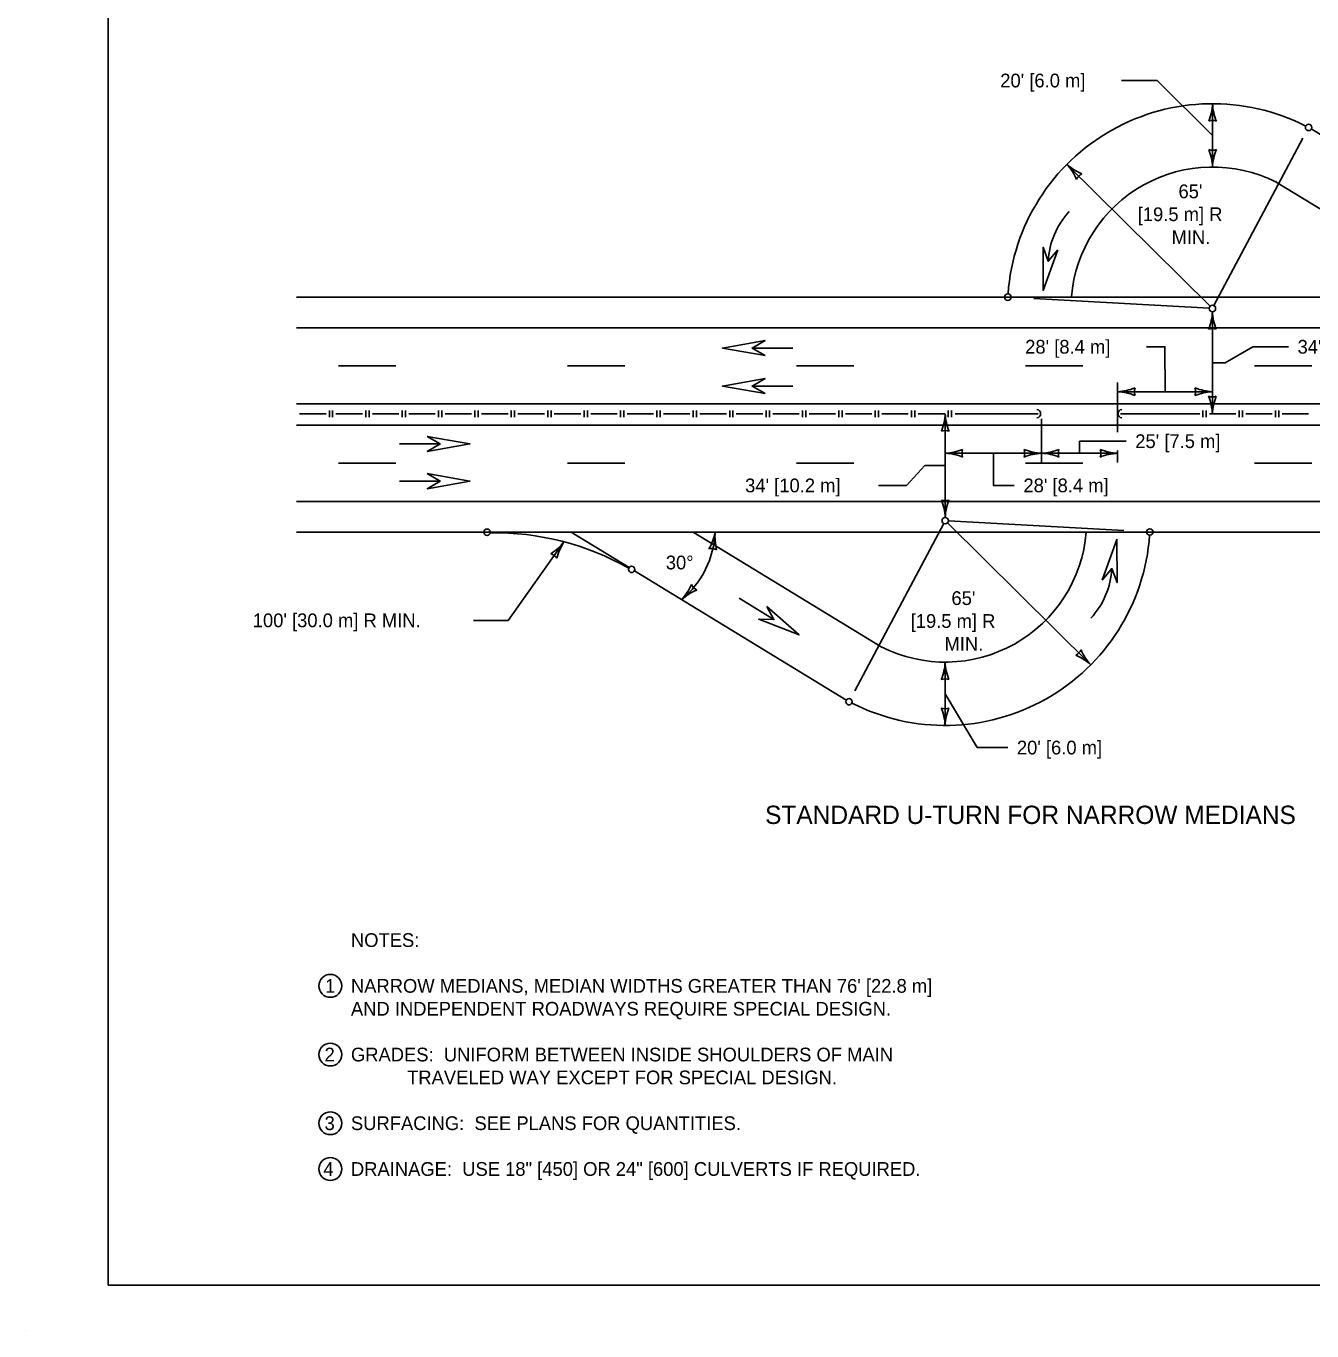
# Model space of a CAD drawing. Extents: x 49991.4 to 50021, y 49987.6 to 50011.4.
# Drawn here: x 49999.98 to 50005.59, y 49999.86 to 50005.56 of the extents above; entities that cross this region are included whole.
import ezdxf

# ---------------------------------------------------------------- set-up
doc = ezdxf.new("R2010")
doc.units = 0
for name, color, linetype in [('Level 1', 7, 'Continuous'), ('Level 2', 7, 'Continuous'), ('Level 3', 7, 'Continuous')]:
    doc.layers.add(name, color=color, linetype=linetype)

msp = doc.modelspace()

# ---------------------------------------------------------------- linework, layer by layer
at = {"layer": 'Level 1'}
for p, q in [((50006.5134, 50004.5478), (50005.5905, 50005.1118)), ((50006.2573, 50004.3784), (50005.4358, 50004.8804)), ((50001.1572, 50004.3784), (50007.9905, 50004.3784)), ((50001.1572, 50004.2451), (50007.9905, 50004.2451)), ((50003.3244, 50004.1562), (50003.1465, 50004.1562)), ((50001.3404, 50004.0784), (50001.5904, 50004.0784)), ((50002.3404, 50004.0784), (50002.5904, 50004.0784)), ((50003.3404, 50004.0784), (50003.5904, 50004.0784)), ((50004.3404, 50004.0784), (50004.5904, 50004.0784)), ((50005.3404, 50004.0784), (50005.5904, 50004.0784)), ((50003.3244, 50003.9897), (50003.1465, 50003.9897)), ((50001.1572, 50003.9118), (50007.9905, 50003.9118)), ((50001.3007, 50003.8548), (50001.3007, 50003.8836)), ((50001.3152, 50003.8548), (50001.3152, 50003.8836)), ((50001.4596, 50003.8548), (50001.4596, 50003.8836)), ((50001.4741, 50003.8548), (50001.4741, 50003.8836)), ((50001.6186, 50003.8548), (50001.6186, 50003.8836)), ((50001.633, 50003.8548), (50001.633, 50003.8836)), ((50001.7775, 50003.8548), (50001.7775, 50003.8836)), ((50001.7919, 50003.8548), (50001.7919, 50003.8836)), ((50001.9364, 50003.8548), (50001.9364, 50003.8836)), ((50001.9508, 50003.8548), (50001.9508, 50003.8836)), ((50002.0953, 50003.8548), (50002.0953, 50003.8836)), ((50002.1098, 50003.8548), (50002.1098, 50003.8836)), ((50002.2542, 50003.8548), (50002.2542, 50003.8836)), ((50002.2687, 50003.8548), (50002.2687, 50003.8836)), ((50002.4131, 50003.8548), (50002.4131, 50003.8836)), ((50002.4276, 50003.8548), (50002.4276, 50003.8836)), ((50002.5721, 50003.8548), (50002.5721, 50003.8836)), ((50002.5865, 50003.8548), (50002.5865, 50003.8836)), ((50002.731, 50003.8548), (50002.731, 50003.8836)), ((50002.7454, 50003.8548), (50002.7454, 50003.8836)), ((50002.8899, 50003.8548), (50002.8899, 50003.8836)), ((50002.9043, 50003.8548), (50002.9043, 50003.8836)), ((50003.0488, 50003.8548), (50003.0488, 50003.8836)), ((50003.0632, 50003.8548), (50003.0632, 50003.8836)), ((50003.2077, 50003.8548), (50003.2077, 50003.8836)), ((50003.2222, 50003.8548), (50003.2222, 50003.8836)), ((50003.3666, 50003.8548), (50003.3666, 50003.8836)), ((50003.3811, 50003.8548), (50003.3811, 50003.8836)), ((50003.5255, 50003.8548), (50003.5255, 50003.8836)), ((50003.54, 50003.8548), (50003.54, 50003.8836)), ((50003.6845, 50003.8548), (50003.6845, 50003.8836)), ((50003.6989, 50003.8548), (50003.6989, 50003.8836)), ((50003.8434, 50003.8548), (50003.8434, 50003.8836)), ((50003.8578, 50003.8548), (50003.8578, 50003.8836)), ((50004.0023, 50003.8548), (50004.0023, 50003.8836)), ((50004.0167, 50003.8548), (50004.0167, 50003.8836)), ((50005.1147, 50003.8548), (50005.1147, 50003.8836)), ((50005.1291, 50003.8548), (50005.1291, 50003.8836)), ((50005.2736, 50003.8548), (50005.2736, 50003.8836)), ((50005.288, 50003.8548), (50005.288, 50003.8836)), ((50005.4325, 50003.8548), (50005.4325, 50003.8836)), ((50005.447, 50003.8548), (50005.447, 50003.8836)), ((50007.9905, 50003.8192), (50001.1572, 50003.8192)), ((50001.6072, 50003.7372), (50001.7851, 50003.7372)), ((50001.3404, 50003.6525), (50001.5904, 50003.6525)), ((50002.3404, 50003.6525), (50002.5904, 50003.6525)), ((50003.3404, 50003.6525), (50003.5904, 50003.6525)), ((50004.3404, 50003.6525), (50004.5904, 50003.6525)), ((50005.3404, 50003.6525), (50005.5904, 50003.6525)), ((50001.6072, 50003.5746), (50001.7851, 50003.5746)), ((50007.9905, 50003.4859), (50001.1572, 50003.4859)), ((50007.9905, 50003.3525), (50001.1572, 50003.3525)), ((50002.3563, 50003.3525), (50002.6096, 50003.1977)), ((50002.8897, 50003.3525), (50003.711, 50002.8506)), ((50002.6339, 50003.1829), (50003.5563, 50002.6192)), ((50003.0901, 50003.0628), (50003.2419, 50002.97)), ((49999.9766, 49999.8624), (49999.9766, 49999.8624))]:
    msp.add_line(p, q, dxfattribs=at)
for points in [[(50008.6146, 50011.2628), (50000.3356, 50011.2628), (50000.3356, 50000.0624), (50008.6146, 50000.0624)], [(50004.4819, 50004.5852), (50004.4172, 50004.4076), (50004.4171, 50004.5967), (50004.4397, 50004.535)], [(50003.2034, 50004.1234), (50003.0172, 50004.1562), (50003.2034, 50004.1892), (50003.1466, 50004.1562)], [(50003.2034, 50003.9569), (50003.0172, 50003.9897), (50003.2034, 50004.0227), (50003.1466, 50003.9897)], [(50001.7282, 50003.7702), (50001.9144, 50003.7374), (50001.7282, 50003.7044), (50001.785, 50003.7374)], [(50001.7282, 50003.6076), (50001.9144, 50003.5748), (50001.7282, 50003.5418), (50001.785, 50003.5748)], [(50004.6753, 50003.1427), (50004.74, 50003.3203), (50004.7401, 50003.1312), (50004.7175, 50003.1929)], [(50003.2105, 50003.0277), (50003.3522, 50002.9026), (50003.1761, 50002.9715), (50003.2418, 50002.9701)]]:
    msp.add_lwpolyline(points, close=True, dxfattribs=at)
for points in [[(50001.1707, 50003.8692), (50001.2863, 50003.8692)], [(50001.3296, 50003.8692), (50001.4452, 50003.8692)], [(50001.4885, 50003.8692), (50001.6041, 50003.8692)], [(50001.6475, 50003.8692), (50001.763, 50003.8692)], [(50001.8064, 50003.8692), (50001.9219, 50003.8692)], [(50001.9653, 50003.8692), (50002.0809, 50003.8692)], [(50002.1242, 50003.8692), (50002.2398, 50003.8692)], [(50002.2831, 50003.8692), (50002.3987, 50003.8692)], [(50002.442, 50003.8692), (50002.5576, 50003.8692)], [(50002.601, 50003.8692), (50002.7165, 50003.8692)], [(50002.7599, 50003.8692), (50002.8754, 50003.8692)], [(50002.9188, 50003.8692), (50003.0343, 50003.8692)], [(50003.0777, 50003.8692), (50003.1933, 50003.8692)], [(50003.2366, 50003.8692), (50003.3522, 50003.8692)], [(50003.3955, 50003.8692), (50003.5111, 50003.8692)], [(50003.5544, 50003.8692), (50003.67, 50003.8692)], [(50003.7133, 50003.8692), (50003.8289, 50003.8692)], [(50003.8722, 50003.8692), (50003.9886, 50003.8692)], [(50004.0336, 50003.8692), (50004.3957, 50003.8692)], [(50004.7555, 50003.8692), (50005.1025, 50003.8692)], [(50005.1436, 50003.8692), (50005.2592, 50003.8692)], [(50005.3025, 50003.8692), (50005.4181, 50003.8692)], [(50005.4614, 50003.8692), (50005.577, 50003.8692)]]:
    msp.add_lwpolyline(points, dxfattribs=at)
for centre in [(50005.5768, 50005.1199), (50004.2634, 50004.3784), (50001.9894, 50003.3516), (50004.8834, 50003.3526), (50002.6207, 50003.1892), (50003.57, 50002.611)]:
    msp.add_circle(centre, 0.014, dxfattribs=at)
for centre, radius, start, end in [((50005.1572, 50004.3284), 0.8952, 62.9695, 175.9019), ((50005.1572, 50004.3284), 0.8952, 61.049, 61.1752), ((50005.1572, 50004.3284), 0.6184, 63.2177, 175.2872), ((50004.7883, 50004.5156), 0.3492, 137.3302, 176.8211), ((50004.3884, 50003.8696), 0.0183, 276.655, 82.9237), ((50004.7628, 50003.8696), 0.0183, 97.0763, 263.345), ((50003.9896, 50003.4025), 0.6184, 243.2177, 355.2872), ((50002.0184, 50002.1501), 1.1993, 60.566, 90.7233), ((50003.9896, 50003.4025), 0.8952, 242.9695, 355.9019), ((50004.3689, 50003.2123), 0.3492, 317.3302, 356.8211), ((50003.9896, 50003.4025), 0.8952, 241.049, 241.1752)]:
    msp.add_arc(centre, radius, start, end, dxfattribs=at)
at = {"layer": 'Level 2'}
for centre in [(50001.305, 50001.3697), (50001.305, 50001.0697), (50001.305, 50000.7697), (50001.305, 50000.5697)]:
    msp.add_circle(centre, 0.05, dxfattribs=at)
at = {"layer": 'Level 3'}
for p, q in [((50004.9158, 50005.3248), (50004.7596, 50005.3248)), ((50005.1572, 50005.0852), (50004.9158, 50005.3248)), ((50005.1572, 50004.9468), (50005.1572, 50005.2236)), ((50005.1633, 50004.3413), (50005.5514, 50005.0723)), ((50005.1467, 50004.3388), (50004.5214, 50004.9586)), ((50005.1427, 50004.3297), (50004.3773, 50004.3721)), ((50005.1567, 50004.3149), (50005.1567, 50003.8692)), ((50005.2131, 50004.092), (50005.3325, 50004.1617)), ((50005.4885, 50004.1617), (50005.3325, 50004.1617)), ((50005.1567, 50004.092), (50005.2131, 50004.092)), ((50004.7429, 50004.0055), (50004.7429, 50003.7892)), ((50005.1567, 50003.9655), (50004.7429, 50003.9655)), ((50003.9901, 50003.4161), (50003.9901, 50003.8692)), ((50004.4106, 50003.6564), (50004.4106, 50003.8472)), ((50003.9901, 50003.6964), (50004.4106, 50003.6964)), ((50004.4106, 50003.6964), (50004.7429, 50003.6964)), ((50004.7429, 50003.6964), (50004.7429, 50003.7092)), ((50004.7429, 50003.6964), (50004.7429, 50003.6564)), ((50003.9835, 50003.3897), (50003.5954, 50002.6587)), ((50004.0001, 50003.3922), (50004.6254, 50002.7724)), ((50004.0041, 50003.4013), (50004.7696, 50003.3589)), ((50002.0819, 50002.9666), (50002.3251, 50003.3095)), ((50001.9301, 50002.9666), (50002.0819, 50002.9666)), ((50003.9896, 50002.7841), (50003.9896, 50002.5073)), ((50003.9896, 50002.6457), (50004.129, 50002.4108)), ((50004.129, 50002.4108), (50004.2629, 50002.4108))]:
    msp.add_line(p, q, dxfattribs=at)
for points in [[(50004.9498, 50003.9655), (50004.9496, 50004.1617), (50004.8683, 50004.1617)], [(50004.2003, 50003.6964), (50004.2004, 50003.5559), (50004.2915, 50003.5559)], [(50004.5768, 50003.6964), (50004.5769, 50003.7492), (50004.7798, 50003.7492)], [(50003.9901, 50003.6427), (50003.9003, 50003.6427), (50003.8207, 50003.5559), (50003.6993, 50003.5559)]]:
    msp.add_lwpolyline(points, dxfattribs=at)
for centre in [(50005.1567, 50004.3289), (50003.9901, 50003.4021)]:
    msp.add_circle(centre, 0.014, dxfattribs=at)
for centre, radius, start, end in [((50004.9351, 50005.2328), 0.2223, 337.456, 357.6395), ((50005.3899, 50005.2351), 0.233, 182.8273, 202.0772), ((50005.1572, 50005.0954), 0.0548, 72.1388, 107.8612), ((50005.1572, 50005.0751), 0.0548, 252.1388, 287.8612), ((50004.9245, 50004.9354), 0.233, 2.8273, 22.0772), ((50005.3793, 50004.9377), 0.2223, 157.456, 177.6395), ((50004.3585, 50004.8073), 0.2223, 22.7092, 42.8927), ((50004.677, 50005.132), 0.233, 228.0805, 247.3303), ((50004.6124, 50004.8684), 0.0548, 117.392, 153.1144), ((50004.9346, 50004.324), 0.2223, 337.456, 357.6395), ((50005.3894, 50004.3264), 0.233, 182.8273, 202.0772), ((50005.1567, 50004.1866), 0.0548, 72.1388, 107.8612), ((50004.7314, 50004.1982), 0.233, 272.8273, 292.0772), ((50004.8711, 50003.9655), 0.0548, 162.1388, 197.8612), ((50005.1659, 50004.1876), 0.2223, 247.456, 267.6395), ((50005.0285, 50003.9655), 0.0548, 342.1388, 17.8612), ((50004.7337, 50003.7434), 0.2223, 67.456, 87.6395), ((50005.1682, 50003.7328), 0.233, 92.8273, 112.0772), ((50005.1567, 50003.9974), 0.0548, 252.1388, 287.8612), ((50004.924, 50003.8577), 0.233, 2.8273, 22.0772), ((50005.3788, 50003.86), 0.2223, 157.456, 177.6395), ((50003.768, 50003.8784), 0.2223, 337.456, 357.6395), ((50004.2228, 50003.8807), 0.233, 182.8273, 202.0772), ((50003.9901, 50003.741), 0.0548, 72.1388, 107.8612), ((50003.9786, 50003.9291), 0.233, 272.8273, 292.0772), ((50003.9809, 50003.4743), 0.2223, 67.456, 87.6395), ((50004.1183, 50003.6964), 0.0548, 162.1388, 197.8612), ((50004.4198, 50003.9185), 0.2223, 247.456, 267.6395), ((50004.2824, 50003.6964), 0.0548, 342.1388, 17.8612), ((50004.4221, 50003.4637), 0.233, 92.8273, 112.0772), ((50004.3991, 50003.9291), 0.233, 272.8273, 292.0772), ((50004.4014, 50003.4743), 0.2223, 67.456, 87.6395), ((50004.5388, 50003.6964), 0.0548, 162.1388, 197.8612), ((50004.7521, 50003.9185), 0.2223, 247.456, 267.6395), ((50004.6147, 50003.6964), 0.0548, 342.1388, 17.8612), ((50004.7544, 50003.4637), 0.233, 92.8273, 112.0772), ((50003.9901, 50003.5443), 0.0548, 252.1388, 287.8612), ((50003.7574, 50003.4046), 0.233, 2.8273, 22.0772), ((50004.2122, 50003.4069), 0.2223, 157.456, 177.6395), ((50002.5791, 50003.37), 0.4068, 309.7634, 357.528), ((50002.7668, 50003.3922), 0.2223, 329.5261, 349.7097), ((50003.2176, 50003.3318), 0.233, 174.8974, 194.1473), ((50002.1492, 50003.4455), 0.2223, 302.11, 322.2936), ((50002.5216, 50003.1842), 0.233, 147.4813, 166.7312), ((50002.2509, 50003.2049), 0.0548, 36.7929, 72.5152), ((50002.9678, 50003.2255), 0.0548, 64.209, 99.9313), ((50002.6672, 50003.2144), 0.233, 317.6233, 336.8731), ((50002.9893, 50002.8933), 0.2223, 112.252, 132.4355), ((50002.9303, 50003.1477), 0.0548, 206.9348, 242.6571), ((50003.7675, 50002.7933), 0.2223, 337.456, 357.6395), ((50004.2223, 50002.7956), 0.233, 182.8273, 202.0772), ((50004.5344, 50002.8626), 0.0548, 297.392, 333.1144), ((50004.4698, 50002.599), 0.233, 48.0805, 67.3303), ((50004.7883, 50002.9237), 0.2223, 202.7092, 222.8927), ((50003.9896, 50002.6559), 0.0548, 72.1388, 107.8612), ((50003.9896, 50002.6355), 0.0548, 252.1388, 287.8612), ((50003.7569, 50002.4958), 0.233, 2.8273, 22.0772), ((50004.2117, 50002.4982), 0.2223, 157.456, 177.6395)]:
    msp.add_arc(centre, radius, start, end, dxfattribs=at)

# ---------------------------------------------------------------- texts
at = {"layer": 'Level 2'}
for s, height, p in [("20' [6.0 m]", 0.06, (50004.2303, 50005.2948)), ("65'", 0.06, (50005.0086, 50004.8107)), ('[19.5 m] R', 0.06, (50004.8305, 50004.7107)), ('MIN.', 0.06, (50004.9783, 50004.6107)), ("28' [8.4 m]", 0.06, (50004.3391, 50004.1317)), ("34' [10.2 m]", 0.06, (50005.5285, 50004.1317)), ("25' [7.5 m]", 0.06, (50004.8198, 50003.7192)), ("34' [10.2 m]", 0.06, (50003.1162, 50003.5259)), ("28' [8.4 m]", 0.06, (50004.3315, 50003.5259)), ('30°', 0.06, (50002.7699, 50003.1892)), ("65'", 0.06, (50004.0172, 50003.0336)), ("100' [30.0 m] R MIN.", 0.06, (50000.9663, 50002.9366)), ('[19.5 m] R', 0.06, (50003.839, 50002.9336)), ('MIN.', 0.06, (50003.9868, 50002.8336)), ("20' [6.0 m]", 0.06, (50004.3029, 50002.3808)), ('STANDARD U-TURN FOR NARROW MEDIANS', 0.08, (50003.2033, 50002.077)), ('NOTES:', 0.06, (50001.395, 50001.5397)), ('1', 0.06, (50001.2823, 50001.3397)), ("NARROW MEDIANS, MEDIAN WIDTHS GREATER THAN 76' [22.8 m] ", 0.06, (50001.395, 50001.3397)), ('AND INDEPENDENT ROADWAYS REQUIRE SPECIAL DESIGN.', 0.06, (50001.395, 50001.2397)), ('2', 0.06, (50001.2798, 50001.0397)), ('GRADES:  UNIFORM BETWEEN INSIDE SHOULDERS OF MAIN', 0.06, (50001.395, 50001.0397)), ('           TRAVELED WAY EXCEPT FOR SPECIAL DESIGN.', 0.06, (50001.395, 50000.9397)), ('3', 0.06, (50001.2798, 50000.7397)), ('SURFACING:  SEE PLANS FOR QUANTITIES.', 0.06, (50001.395, 50000.7397)), ('4', 0.06, (50001.2747, 50000.5397)), ('DRAINAGE:  USE 18" [450] OR 24" [600] CULVERTS IF REQUIRED.', 0.06, (50001.395, 50000.5397))]:
    msp.add_text(s, height=height, dxfattribs=at).set_placement(p)

doc.saveas('drawing.dxf')
